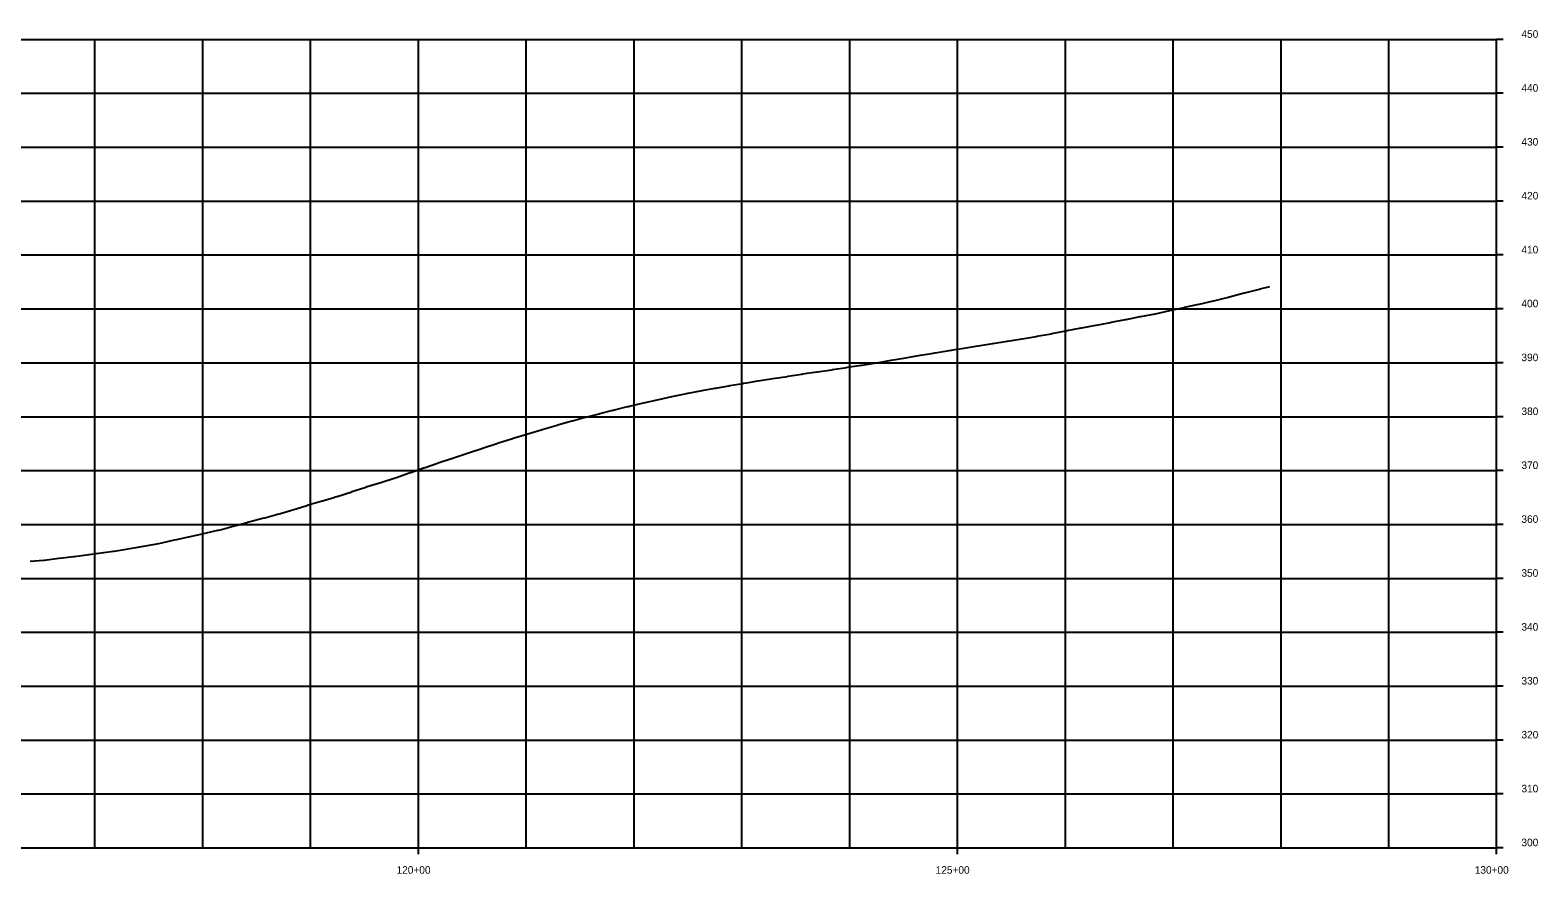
# Model space of a CAD drawing. Extents: x 1627557 to 1636561, y 783843 to 794002.
# Drawn here: x 1634732 to 1636131, y 793194 to 793977 of the extents above; entities that cross this region are included whole.
import ezdxf

# ---------------------------------------------------------------- set-up
doc = ezdxf.new("R2010")
doc.units = 0
for name, color, linetype in [('R_Axis', 7, 'Continuous'), ('R_Axis Annot', 7, 'Continuous'), ('R_Exist Surface', 7, 'Continuous'), ('R_Grid', 7, 'Continuous')]:
    doc.layers.add(name, color=color, linetype=linetype)

msp = doc.modelspace()

# ---------------------------------------------------------------- linework, layer by layer
at = {"layer": 'R_Axis'}
for p, q in [((1636092.6, 793218.6), (1636092.6, 793968.6)), ((1636098.6, 793968.6), (1636092.6, 793968.6)), ((1636098.6, 793968.6), (1636092.6, 793968.6)), ((1636098.6, 793918.6), (1636092.6, 793918.6)), ((1636098.6, 793868.6), (1636092.6, 793868.6)), ((1636098.6, 793818.6), (1636092.6, 793818.6)), ((1636098.6, 793768.6), (1636092.6, 793768.6)), ((1636098.6, 793718.6), (1636092.6, 793718.6)), ((1636098.6, 793668.6), (1636092.6, 793668.6)), ((1636098.6, 793618.6), (1636092.6, 793618.6)), ((1636098.6, 793568.6), (1636092.6, 793568.6)), ((1636098.6, 793518.6), (1636092.6, 793518.6)), ((1636098.6, 793468.6), (1636092.6, 793468.6)), ((1636098.6, 793418.6), (1636092.6, 793418.6)), ((1636098.6, 793368.6), (1636092.6, 793368.6)), ((1636098.6, 793318.6), (1636092.6, 793318.6)), ((1636098.6, 793268.6), (1636092.6, 793268.6)), ((1633092.6, 793218.6), (1636092.6, 793218.6)), ((1635092.6, 793212.6), (1635092.6, 793218.6)), ((1635592.6, 793212.6), (1635592.6, 793218.6)), ((1636098.6, 793218.6), (1636092.6, 793218.6)), ((1636092.6, 793212.6), (1636092.6, 793218.6))]:
    msp.add_line(p, q, dxfattribs=at)
at = {"layer": 'R_Exist Surface'}
msp.add_lwpolyline([(1634732.4, 793484.7), (1634745.1, 793485.5), (1634745.8, 793485.5), (1634759, 793487.2), (1634759.5, 793487.3), (1634772.9, 793489), (1634773.2, 793489), (1634773.5, 793489), (1634787, 793490.7), (1634787.1, 793490.7), (1634793.7, 793491.6), (1634800.7, 793492.5), (1634800.7, 793492.5), (1634809.9, 793493.7), (1634810.4, 793493.8), (1634832.3, 793497.6), (1634851.7, 793501.1), (1634851.9, 793501.1), (1634854.7, 793501.6), (1634866.3, 793504.2), (1634868.5, 793504.7), (1634879.2, 793507.1), (1634879.6, 793507.2), (1634882.3, 793507.8), (1634893.5, 793510.3), (1634896.1, 793510.9), (1634906.5, 793513.2), (1634907.4, 793513.4), (1634909.8, 793514), (1634920.9, 793517), (1634923.2, 793517.7), (1634933.7, 793520.5), (1634934.2, 793520.6), (1634936.6, 793521.3), (1634948.1, 793524.4), (1634950, 793524.9), (1634961, 793527.8), (1634962, 793528.1), (1634963.4, 793528.5), (1634964.7, 793528.9), (1634976.9, 793532.6), (1634988.3, 793536), (1634989.1, 793536.3), (1634990.3, 793536.7), (1635003.2, 793540.5), (1635003.7, 793540.6), (1635014, 793543.7), (1635015.5, 793544.1), (1635016.9, 793544.5), (1635017.1, 793544.6), (1635030.7, 793549), (1635030.9, 793549.1), (1635042.8, 793553), (1635044.4, 793553.5), (1635044.7, 793553.7), (1635045.1, 793553.8), (1635058.5, 793558), (1635059.5, 793558.3), (1635070.1, 793561.7), (1635072.2, 793562.3), (1635084, 793566.4), (1635085.5, 793566.9), (1635097.3, 793571.1), (1635097.4, 793571.1), (1635098.7, 793571.5), (1635110.2, 793575.4), (1635111.9, 793576), (1635123.1, 793579.7), (1635124.6, 793580.2), (1635125.1, 793580.4), (1635137.2, 793584.4), (1635138.9, 793585), (1635151.4, 793589.2), (1635151.9, 793589.4), (1635152.8, 793589.7), (1635165.2, 793593.7), (1635166.7, 793594.2), (1635178.9, 793598.1), (1635179.1, 793598.2), (1635180.5, 793598.6), (1635193, 793602.4), (1635194.1, 793602.7), (1635206.4, 793606.4), (1635207.3, 793606.7), (1635207.8, 793606.8), (1635208.3, 793607), (1635221.4, 793610.8), (1635221.8, 793610.9), (1635233.7, 793614.3), (1635235.1, 793614.7), (1635235.4, 793614.8), (1635244, 793617.1), (1635247.8, 793618.1), (1635247.9, 793618.1), (1635260.1, 793621.3), (1635260.8, 793621.4), (1635260.9, 793621.5), (1635272.9, 793624.5), (1635273.6, 793624.7), (1635274.4, 793624.9), (1635286.4, 793627.9), (1635287.4, 793628.1), (1635288.2, 793628.3), (1635300.1, 793631), (1635301.5, 793631.3), (1635313.9, 793634.1), (1635315.5, 793634.5), (1635315.6, 793634.5), (1635327.6, 793637.2), (1635340, 793639.9), (1635341.3, 793640.2), (1635342.5, 793640.4), (1635342.7, 793640.5), (1635354.3, 793642.6), (1635355.6, 793642.8), (1635367.4, 793644.9), (1635368.7, 793645.1), (1635370, 793645.4), (1635380.4, 793647.2), (1635381.4, 793647.4), (1635393.5, 793649.5), (1635394, 793649.6), (1635397.3, 793650.1), (1635407.3, 793651.7), (1635407.6, 793651.8), (1635419.4, 793653.6), (1635421.2, 793653.9), (1635421.2, 793653.9), (1635434.8, 793656), (1635435.1, 793656.1), (1635448.3, 793658.1), (1635448.9, 793658.2), (1635462.1, 793660.2), (1635462.7, 793660.3), (1635476, 793662.2), (1635476.5, 793662.3), (1635489.8, 793664.3), (1635490.3, 793664.4), (1635503.6, 793666.3), (1635504.1, 793666.4), (1635517.2, 793668.7), (1635517.6, 793668.7), (1635530.9, 793671), (1635531.1, 793671), (1635544.6, 793673.3), (1635544.6, 793673.3), (1635544.6, 793673.3), (1635547.6, 793673.8), (1635558.1, 793675.6), (1635558.2, 793675.6), (1635568.3, 793677.2), (1635571.5, 793677.7), (1635571.8, 793677.8), (1635584.9, 793680), (1635585, 793680), (1635590.5, 793680.9), (1635598.4, 793682.1), (1635611.5, 793684.3), (1635611.8, 793684.3), (1635625, 793686.5), (1635625.4, 793686.5), (1635638.6, 793688.7), (1635639, 793688.7), (1635652.1, 793690.9), (1635652.6, 793690.9), (1635665.6, 793693.1), (1635666.2, 793693.2), (1635679.3, 793695.6), (1635679.9, 793695.7), (1635693, 793698.2), (1635693.6, 793698.3), (1635694.2, 793698.4), (1635707.2, 793700.9), (1635707.9, 793701), (1635720.9, 793703.5), (1635721.6, 793703.6), (1635734.6, 793706.1), (1635735.2, 793706.2), (1635748.4, 793708.8), (1635748.9, 793708.9), (1635762.1, 793711.4), (1635762.5, 793711.5), (1635775.8, 793714.1), (1635776.2, 793714.1), (1635789.4, 793717.1), (1635802.7, 793720), (1635803.1, 793720.1), (1635816.3, 793723), (1635816.7, 793723.1), (1635829.9, 793726), (1635830.3, 793726.1), (1635844, 793729.6), (1635844.4, 793729.7), (1635844.9, 793729.8), (1635858.5, 793733.4), (1635859.1, 793733.5), (1635872.7, 793737), (1635873.2, 793737.2), (1635882.1, 793739.5)], dxfattribs=at)
at = {"layer": 'R_Grid'}
for p, q in [((1633092.6, 793968.6), (1636092.6, 793968.6)), ((1633092.6, 793968.6), (1636092.6, 793968.6)), ((1634792.6, 793218.6), (1634792.6, 793968.6)), ((1634892.6, 793218.6), (1634892.6, 793968.6)), ((1634992.6, 793218.6), (1634992.6, 793968.6)), ((1635092.6, 793218.6), (1635092.6, 793968.6)), ((1635192.6, 793218.6), (1635192.6, 793968.6)), ((1635292.6, 793218.6), (1635292.6, 793968.6)), ((1635392.6, 793218.6), (1635392.6, 793968.6)), ((1635492.6, 793218.6), (1635492.6, 793968.6)), ((1635592.6, 793218.6), (1635592.6, 793968.6)), ((1635692.6, 793218.6), (1635692.6, 793968.6)), ((1635792.6, 793218.6), (1635792.6, 793968.6)), ((1635892.6, 793218.6), (1635892.6, 793968.6)), ((1635992.6, 793218.6), (1635992.6, 793968.6)), ((1633092.6, 793918.6), (1636092.6, 793918.6)), ((1633092.6, 793868.6), (1636092.6, 793868.6)), ((1633092.6, 793818.6), (1636092.6, 793818.6)), ((1633092.6, 793768.6), (1636092.6, 793768.6)), ((1633092.6, 793718.6), (1636092.6, 793718.6)), ((1633092.6, 793668.6), (1636092.6, 793668.6)), ((1633092.6, 793618.6), (1636092.6, 793618.6)), ((1633092.6, 793568.6), (1636092.6, 793568.6)), ((1633092.6, 793518.6), (1636092.6, 793518.6)), ((1633092.6, 793468.6), (1636092.6, 793468.6)), ((1633092.6, 793418.6), (1636092.6, 793418.6)), ((1633092.6, 793368.6), (1636092.6, 793368.6)), ((1633092.6, 793318.6), (1636092.6, 793318.6)), ((1633092.6, 793268.6), (1636092.6, 793268.6))]:
    msp.add_line(p, q, dxfattribs=at)

# ---------------------------------------------------------------- texts
at = {"layer": 'R_Axis Annot'}
for s, p in [('450', (1636115.6, 793970.1)), ('450', (1636115.6, 793970.1)), ('440', (1636115.6, 793920.1)), ('430', (1636115.6, 793870.1)), ('420', (1636115.6, 793820.1)), ('410', (1636115.6, 793770.1)), ('400', (1636115.6, 793720.1)), ('390', (1636115.6, 793670.1)), ('380', (1636115.6, 793620.1)), ('370', (1636115.6, 793570.1)), ('360', (1636115.6, 793520.1)), ('350', (1636115.6, 793470.1)), ('340', (1636115.6, 793420.1)), ('330', (1636115.6, 793370.1)), ('320', (1636115.6, 793320.1)), ('310', (1636115.6, 793270.1)), ('300', (1636115.6, 793220.1)), ('120+00', (1635072.3, 793194.6)), ('125+00', (1635572.3, 793194.6)), ('130+00', (1636072.3, 793194.6))]:
    msp.add_text(s, height=7, dxfattribs=at).set_placement(p)

doc.saveas('drawing.dxf')
